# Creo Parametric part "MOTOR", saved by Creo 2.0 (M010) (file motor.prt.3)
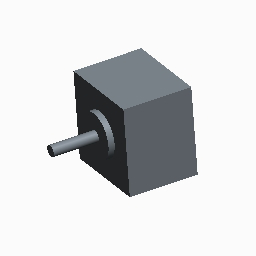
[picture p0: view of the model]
Units: Inch lbm Second (Pro/E Default); INCH, POUND, SECS

Created from: INLBS_PART_SOLID.PRT

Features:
  1. datum plane "RIGHT"
  2. datum plane "TOP"
  3. datum plane "FRONT"
  4. coordinate system
  5. sketch "Sketch 1"
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
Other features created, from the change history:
  extrusion "Extrude 1"
  sketch "Sketch 2"
  extrusion "Extrude 2"
  sketch "Sketch 3"
  extrusion "Extrude 3"

Surfaces: 11 plane, 4 cylinder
